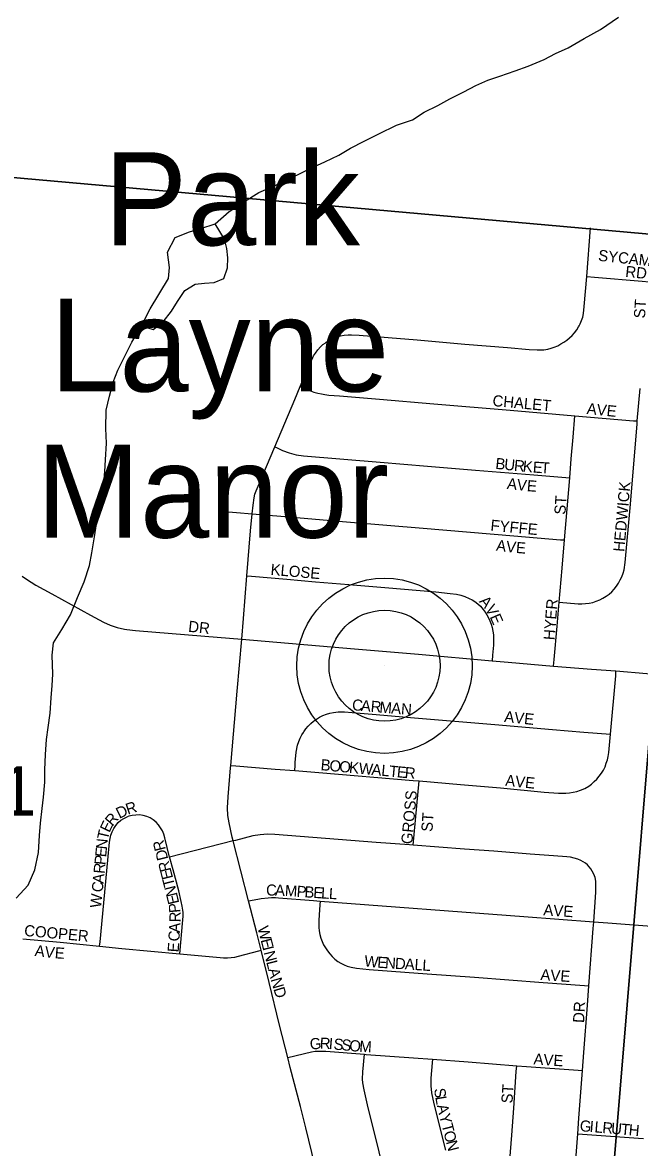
# Model space of a CAD drawing. Extents: x 0 to 680, y 0 to 440.
# Drawn here: x 150.24 to 158.43, y 273.01 to 287.97 of the extents above; entities that cross this region are included whole.
import ezdxf

# ---------------------------------------------------------------- set-up
doc = ezdxf.new("R2010")
doc.units = 0
for name, color, linetype in [('GM_X_Minor_Lake', 7, 'Continuous'), ('GM_X_Minor_River', 7, 'Continuous'), ('GM_X_Section', 7, 'Continuous'), ('GM_X_Section_Text', 7, 'Continuous'), ('GM_X_Township_Subdivision', 7, 'Continuous'), ('GM_X_Township_Subdivision_Text', 7, 'Continuous'), ('GM_X_Unincorporated', 7, 'Continuous'), ('GM_X_Unincorporated_Location', 7, 'Continuous'), ('GM_X_Unincorporated_Text', 7, 'Continuous')]:
    doc.layers.add(name, color=color, linetype=linetype)

msp = doc.modelspace()

# ---------------------------------------------------------------- linework, layer by layer
at = {"layer": 'GM_X_Minor_Lake'}
for points in [[(151.818, 283.935), (151.972, 283.886), (152.104, 283.985), (152.218, 284.126), (152.297, 284.256), (152.394, 284.403), (152.531, 284.485), (152.656, 284.501), (152.781, 284.511), (152.912, 284.563), (152.962, 284.705), (152.963, 284.836), (152.953, 284.96), (152.919, 285.086), (152.797, 285.289)], [(151.818, 283.935), (151.934, 284.159), (152.176, 284.56), (152.19, 284.709), (152.163, 284.911), (152.266, 285.106), (152.457, 285.181), (152.606, 285.226), (152.797, 285.289)]]:
    msp.add_lwpolyline(points, dxfattribs=at)
at = {"layer": 'GM_X_Minor_River'}
for points in [[(152.176, 284.56), (152.19, 284.709), (152.163, 284.911), (152.266, 285.106), (152.457, 285.181), (152.606, 285.226), (152.797, 285.289), (152.983, 285.453), (153.186, 285.587), (153.378, 285.704), (153.586, 285.796), (153.933, 285.964), (154.106, 286.045), (154.255, 286.114), (154.44, 286.201), (154.596, 286.294), (154.775, 286.387), (154.972, 286.486), (155.205, 286.602), (155.42, 286.67), (155.575, 286.775), (155.754, 286.862), (155.916, 286.949), (156.101, 287.042), (156.262, 287.129), (156.418, 287.198), (156.578, 287.25), (156.781, 287.324), (156.954, 287.387), (157.169, 287.474), (157.318, 287.555), (157.485, 287.63), (157.701, 287.752), (157.916, 287.874), (158.155, 288.038)], [(150.15, 276.322), (150.313, 276.498), (150.398, 276.699), (150.449, 276.93), (150.463, 277.155), (150.477, 277.322), (150.497, 277.517), (150.517, 277.666), (150.532, 277.867), (150.534, 278.028), (150.542, 278.236), (150.556, 278.432), (150.576, 278.592), (150.602, 278.782), (150.617, 278.989), (150.631, 279.15), (150.638, 279.304), (150.63, 279.554), (150.65, 279.72), (150.759, 279.896), (150.874, 280.091), (150.966, 280.322), (151.057, 280.528), (151.125, 280.747), (151.157, 280.913), (151.195, 281.127), (151.221, 281.299), (151.259, 281.494), (151.285, 281.643), (151.317, 281.844), (151.331, 281.998), (151.339, 282.153), (151.353, 282.372), (151.344, 282.569), (151.347, 282.812), (151.391, 282.996), (151.441, 283.185), (151.502, 283.345), (151.606, 283.546), (151.691, 283.717), (151.818, 283.935), (151.934, 284.159), (152.176, 284.56)]]:
    msp.add_lwpolyline(points, dxfattribs=at)
at = {"layer": 'GM_X_Section'}
for points in [[(144.694, 302.485), (160.808, 300.853), (159.118, 285.103), (143.238, 286.516), (144.684, 302.372)], [(143.224, 286.379), (143.238, 286.516), (159.118, 285.103), (157.8, 269.245), (141.851, 270.701)], [(159.118, 285.103), (174.94, 283.442), (173.525, 267.764), (158.298, 269.195), (157.8, 269.245)]]:
    msp.add_lwpolyline(points, close=True, dxfattribs=at)
at = {"layer": 'GM_X_Township_Subdivision'}
for points in [[(157.733, 284.59), (157.785, 285.235)], [(153.927, 283.126), (154.043, 283.399), (154.084, 283.491), (154.105, 283.532), (154.128, 283.571), (154.159, 283.614), (154.195, 283.654), (154.229, 283.684), (154.258, 283.703), (154.273, 283.714), (154.32, 283.742), (154.363, 283.764), (154.411, 283.784), (154.462, 283.801), (154.51, 283.809), (154.562, 283.815), (154.61, 283.815), (154.71, 283.81), (155.481, 283.747), (156.114, 283.691), (156.68, 283.644), (156.971, 283.62), (157.073, 283.614), (157.164, 283.616), (157.215, 283.623), (157.263, 283.636), (157.303, 283.65), (157.348, 283.668), (157.389, 283.692), (157.43, 283.716), (157.469, 283.744), (157.506, 283.774), (157.54, 283.806), (157.572, 283.842), (157.601, 283.879), (157.626, 283.919), (157.635, 283.935), (157.648, 283.961), (157.666, 284.005), (157.68, 284.05), (157.689, 284.097), (157.701, 284.19), (157.733, 284.59)], [(157.733, 284.59), (157.839, 284.581), (158.471, 284.526), (158.564, 284.518)], [(153.59, 282.326), (153.855, 282.952), (153.927, 283.126)], [(153.927, 283.126), (154.062, 283.069), (154.109, 283.051), (154.159, 283.036), (154.208, 283.027), (154.253, 283.019), (154.306, 283.012), (154.448, 283.001), (154.979, 282.956), (155.703, 282.895), (156.717, 282.81), (157.577, 282.738)], [(158.405, 282.668), (158.443, 283.098)], [(157.508, 281.912), (157.528, 282.164), (157.553, 282.454), (157.577, 282.738)], [(157.577, 282.738), (158.357, 282.672), (158.405, 282.668)], [(157.369, 280.259), (157.622, 280.237), (157.669, 280.237), (157.719, 280.24), (157.767, 280.246), (157.815, 280.256), (157.861, 280.271), (157.906, 280.289), (157.949, 280.311), (157.991, 280.337), (158.03, 280.366), (158.066, 280.398), (158.1, 280.433), (158.131, 280.471), (158.158, 280.511), (158.18, 280.554), (158.2, 280.598), (158.216, 280.644), (158.229, 280.691), (158.245, 280.787), (158.311, 281.513), (158.402, 282.627), (158.405, 282.668)], [(153.288, 281.435), (153.301, 281.548), (153.313, 281.645), (153.325, 281.695), (153.341, 281.738), (153.379, 281.831), (153.59, 282.326)], [(153.59, 282.326), (153.621, 282.311), (153.692, 282.277), (153.778, 282.245), (153.873, 282.22), (153.969, 282.205), (154.989, 282.121), (155.619, 282.068), (156.255, 282.015), (157.033, 281.95), (157.508, 281.912)], [(157.438, 281.086), (157.508, 281.912)], [(152.87, 281.469), (153.288, 281.435)], [(153.219, 280.61), (153.267, 281.207), (153.288, 281.435)], [(153.288, 281.435), (153.668, 281.402), (154.541, 281.325), (155.561, 281.241), (156.766, 281.139), (157.385, 281.09), (157.438, 281.086)], [(157.369, 280.259), (157.408, 280.71), (157.438, 281.086)], [(150.233, 280.603), (150.288, 280.563), (150.413, 280.486), (150.627, 280.369), (151.139, 280.087), (151.311, 279.994), (151.401, 279.954), (151.495, 279.923), (151.592, 279.901), (151.622, 279.897)], [(153.15, 279.766), (153.172, 280.044), (153.219, 280.61)], [(153.219, 280.61), (153.28, 280.605), (153.748, 280.566), (154.129, 280.531), (154.571, 280.493), (155.051, 280.452), (155.727, 280.395), (155.919, 280.376), (156.004, 280.365), (156.059, 280.354), (156.115, 280.336), (156.173, 280.31), (156.21, 280.29), (156.246, 280.266), (156.286, 280.239), (156.32, 280.205), (156.357, 280.163), (156.383, 280.127), (156.407, 280.089), (156.427, 280.052), (156.447, 280.01), (156.464, 279.966), (156.476, 279.921), (156.486, 279.875), (156.493, 279.826), (156.495, 279.781), (156.493, 279.688), (156.482, 279.554), (156.476, 279.478)], [(157.294, 279.41), (157.302, 279.497), (157.341, 279.938), (157.369, 280.259)], [(151.622, 279.897), (151.737, 279.882), (152.659, 279.808), (153.15, 279.766)], [(153.004, 278.089), (153.088, 279.075), (153.15, 279.766)], [(153.15, 279.766), (154.65, 279.638), (155.499, 279.566), (156.476, 279.478)], [(156.476, 279.478), (156.689, 279.46), (157.294, 279.41)], [(157.294, 279.41), (157.799, 279.37), (158.122, 279.345)], [(158.049, 278.504), (158.12, 279.281), (158.122, 279.345)], [(158.122, 279.345), (158.531, 279.309), (158.97, 279.272)], [(153.854, 278.02), (153.858, 278.088), (153.861, 278.128), (153.874, 278.264), (153.892, 278.359), (153.907, 278.406), (153.926, 278.451), (153.949, 278.495), (153.968, 278.527), (153.973, 278.535), (154, 278.575), (154.033, 278.611), (154.068, 278.645), (154.105, 278.677), (154.143, 278.705), (154.183, 278.732), (154.227, 278.754), (154.274, 278.771), (154.322, 278.785), (154.37, 278.794), (154.429, 278.801), (154.513, 278.801), (154.618, 278.793), (154.935, 278.766), (155.393, 278.724), (156.512, 278.632), (157.28, 278.568), (157.694, 278.532), (158.049, 278.504)], [(155.505, 277.882), (156.055, 277.833), (156.587, 277.791), (157.167, 277.733), (157.36, 277.721), (157.457, 277.72), (157.505, 277.725), (157.554, 277.732), (157.604, 277.743), (157.649, 277.759), (157.709, 277.783), (157.76, 277.813), (157.797, 277.84), (157.834, 277.873), (157.869, 277.907), (157.901, 277.944), (157.93, 277.984), (157.955, 278.027), (157.977, 278.071), (157.994, 278.117), (158.01, 278.163), (158.019, 278.209), (158.027, 278.262), (158.049, 278.504)], [(153.037, 277.085), (153.024, 277.136), (152.981, 277.327), (152.966, 277.424), (152.961, 277.523), (152.967, 277.67), (153.001, 278.057), (153.004, 278.089)], [(153.004, 278.089), (153.07, 278.084), (153.594, 278.041), (153.854, 278.02)], [(153.854, 278.02), (154.173, 277.995), (155.428, 277.888), (155.505, 277.882)], [(155.428, 277.027), (155.505, 277.882)], [(151.261, 275.685), (151.266, 275.742), (151.368, 276.83), (151.393, 277.069), (151.4, 277.116), (151.411, 277.163), (151.428, 277.208), (151.449, 277.251), (151.475, 277.291), (151.507, 277.328), (151.543, 277.359), (151.583, 277.385), (151.627, 277.406)], [(152.191, 276.871), (152.129, 277.126), (152.114, 277.173), (152.095, 277.217), (152.072, 277.26), (152.044, 277.3), (152.011, 277.336), (151.973, 277.367), (151.932, 277.392), (151.887, 277.411), (151.84, 277.423), (151.791, 277.43), (151.743, 277.429), (151.694, 277.424), (151.65, 277.414), (151.627, 277.406)], [(155.428, 277.027), (155.379, 277.031), (154.934, 277.065), (153.587, 277.17), (153.49, 277.173), (153.394, 277.167), (153.299, 277.151), (153.065, 277.092), (153.037, 277.085)], [(153.037, 277.085), (152.191, 276.871)], [(153.241, 276.287), (153.037, 277.085)], [(157.826, 276.011), (157.853, 276.404), (157.856, 276.498), (157.854, 276.549), (157.845, 276.597), (157.829, 276.643), (157.808, 276.685), (157.789, 276.716), (157.767, 276.742), (157.743, 276.767), (157.716, 276.788), (157.686, 276.809), (157.657, 276.825), (157.614, 276.844), (157.568, 276.858), (157.519, 276.868), (157.471, 276.872), (157.292, 276.886), (156.984, 276.909), (156.498, 276.947), (156.109, 276.975), (155.428, 277.027)], [(152.326, 275.584), (152.33, 275.632), (152.362, 275.989), (152.371, 276.085), (152.371, 276.132), (152.367, 276.165), (152.358, 276.216), (152.344, 276.279), (152.313, 276.421), (152.236, 276.702), (152.197, 276.843), (152.191, 276.871)], [(153.241, 276.287), (153.363, 276.311), (153.408, 276.321), (153.5, 276.33), (153.547, 276.334), (153.598, 276.332), (153.64, 276.33), (154.105, 276.293), (154.19, 276.286)], [(153.406, 275.633), (153.349, 275.864), (153.241, 276.287)], [(154.19, 276.286), (154.186, 276.235), (154.181, 276.168), (154.173, 276.033), (154.174, 275.936), (154.18, 275.888), (154.189, 275.841), (154.202, 275.794), (154.218, 275.749), (154.238, 275.705), (154.263, 275.663), (154.291, 275.623), (154.32, 275.585), (154.351, 275.55), (154.387, 275.514), (154.425, 275.483), (154.466, 275.458), (154.51, 275.438), (154.551, 275.421), (154.603, 275.407), (154.673, 275.392), (154.842, 275.376), (155.613, 275.317), (156.241, 275.274), (157.157, 275.204), (157.703, 275.161), (157.762, 275.157)], [(154.19, 276.286), (156.898, 276.081), (157.826, 276.011)], [(157.762, 275.157), (157.82, 275.919), (157.826, 276.011)], [(157.826, 276.011), (158.015, 275.998), (158.708, 275.945)], [(150.24, 275.784), (150.735, 275.738), (151.261, 275.685)], [(151.261, 275.685), (151.556, 275.656), (152.326, 275.584)], [(152.326, 275.584), (152.571, 275.561), (152.862, 275.533), (152.907, 275.531), (152.959, 275.531), (153.057, 275.541), (153.107, 275.551), (153.375, 275.624), (153.406, 275.633)], [(153.761, 274.207), (153.653, 274.637), (153.512, 275.204), (153.406, 275.633)], [(157.679, 274.033), (157.697, 274.271), (157.743, 274.901), (157.762, 275.157)], [(153.761, 274.207), (154.075, 274.281), (154.123, 274.289), (154.171, 274.292), (154.268, 274.289), (154.781, 274.248)], [(154.221, 272.373), (154.198, 272.468), (153.999, 273.271), (153.93, 273.554), (153.795, 274.071), (153.761, 274.207)], [(155.052, 272.634), (154.958, 273.025), (154.828, 273.536), (154.775, 273.774), (154.759, 273.87), (154.756, 273.918), (154.759, 274.016), (154.781, 274.248)], [(154.781, 274.248), (154.801, 274.246), (155.431, 274.201), (155.685, 274.182)], [(155.685, 274.182), (155.681, 274.133), (155.662, 273.929), (155.662, 273.831), (155.672, 273.734), (155.701, 273.591), (155.857, 272.975)], [(155.685, 274.182), (156.158, 274.147), (156.804, 274.097)], [(156.65, 272.046), (156.68, 272.45), (156.737, 273.174), (156.763, 273.534), (156.798, 274.019), (156.804, 274.097)], [(156.804, 274.097), (156.932, 274.087), (157.62, 274.037), (157.679, 274.033)], [(157.616, 273.191), (157.631, 273.398), (157.679, 274.033)], [(157.391, 270.25), (157.43, 270.796), (157.485, 271.506), (157.517, 271.895), (157.576, 272.671), (157.616, 273.191)], [(157.616, 273.191), (158.422, 273.132), (158.486, 273.127)]]:
    msp.add_lwpolyline(points, dxfattribs=at)
at = {"layer": 'GM_X_Unincorporated'}
for radius in [1.165, 0.738]:
    msp.add_circle((155.047, 279.414), radius, dxfattribs=at)
at = {"layer": 'GM_X_Unincorporated_Location'}
msp.add_line((155.047, 279.414), (155.047, 279.414), dxfattribs=at)

# ---------------------------------------------------------------- texts
at = {"layer": 'GM_X_Section_Text'}
msp.add_text('31', height=0.6552, rotation=0, dxfattribs=at).set_placement((149.443, 277.42))
at = {"layer": 'GM_X_Township_Subdivision_Text'}
for s, height, rotation, p in [('SYCAMORE', 0.1482, 354.0691, (157.881, 284.798)), ('RD', 0.1482, 353.994, (158.241, 284.585)), ('ST', 0.1482, 86.4258, (158.507, 284.028)), ('CHALET', 0.1482, 354.8059, (156.477, 282.867)), ('AVE', 0.1482, 354.0969, (157.729, 282.762)), ('B', 0.148, 354.3075, (156.515, 282.032)), ('U', 0.148, 354.3008, (156.632, 282.02)), ('R', 0.148, 354.2954, (156.762, 282.007)), ('K', 0.148, 354.4604, (156.879, 281.996)), ('E', 0.148, 355.7087, (157.013, 281.983)), ('T', 0.148, 356.3866, (157.118, 281.975)), ('A', 0.148, 353.4281, (156.669, 281.766)), ('V', 0.148, 353.6779, (156.799, 281.751)), ('E', 0.148, 355.3295, (156.934, 281.736)), ('HEDWICK', 0.1482, 84.8814, (158.233, 280.924)), ('ST', 0.1482, 86.4258, (157.45, 281.419)), ('FYFFE', 0.1482, 354.56, (156.45, 281.21)), ('A', 0.148, 352.9888, (156.524, 280.944)), ('V', 0.148, 354.0449, (156.656, 280.928)), ('E', 0.148, 355.2976, (156.789, 280.914)), ('KLOSE', 0.1482, 354.9208, (153.528, 280.623)), ('A', 0.148, 311.3658, (156.296, 280.265)), ('HYER', 0.1482, 85.4856, (157.307, 279.75)), ('V', 0.148, 300.4633, (156.378, 280.173)), ('DR', 0.1482, 353.6631, (152.433, 279.867)), ('E', 0.148, 293.595, (156.442, 280.065)), ('C', 0.148, 355.2716, (154.611, 278.823)), ('A', 0.148, 355.2745, (154.728, 278.813)), ('R', 0.148, 355.2716, (154.858, 278.803)), ('M', 0.148, 355.2762, (154.975, 278.793)), ('A', 0.148, 355.2736, (155.131, 278.78)), ('N', 0.148, 355.6236, (155.262, 278.769)), ('AVE', 0.1482, 354.0932, (156.633, 278.667)), ('B', 0.148, 354.6132, (154.193, 278.027)), ('O', 0.148, 354.6156, (154.31, 278.016)), ('O', 0.148, 354.6156, (154.44, 278.004)), ('K', 0.148, 354.6156, (154.57, 277.992)), ('W', 0.148, 354.6123, (154.7, 277.98)), ('A', 0.148, 354.6147, (154.869, 277.964)), ('L', 0.148, 354.6102, (154.999, 277.952)), ('T', 0.148, 354.6124, (155.103, 277.942)), ('E', 0.148, 354.6175, (155.206, 277.932)), ('R', 0.148, 355.0016, (155.311, 277.922)), ('AVE', 0.1482, 354.0936, (156.646, 277.819)), ('GROSS', 0.1482, 84.9208, (155.415, 277.037)), ('R', 0.148, 18.1124, (151.635, 277.432)), ('R', 0.148, 49.5383, (151.43, 277.272)), ('D', 0.148, 25.9003, (151.523, 277.377)), ('ST', 0.1482, 86.4254, (155.683, 277.203)), ('E', 0.148, 64.2659, (151.39, 277.187)), ('T', 0.148, 77.1897, (151.37, 277.093)), ('E', 0.148, 84.322, (151.347, 276.864)), ('N', 0.148, 84.3188, (151.358, 276.968)), ('R', 0.148, 104.3231, (152.142, 276.972)), ('P', 0.148, 84.322, (151.337, 276.76)), ('D', 0.148, 104.3144, (152.174, 276.846)), ('R', 0.148, 84.3382, (151.325, 276.644)), ('R', 0.148, 104.319, (152.213, 276.694)), ('E', 0.148, 104.3282, (152.239, 276.593)), ('A', 0.148, 84.3272, (151.312, 276.514)), ('T', 0.148, 104.3146, (152.264, 276.492)), ('C', 0.148, 84.3264, (151.301, 276.397)), ('N', 0.148, 104.3252, (152.297, 276.365)), ('C', 0.148, 359.8786, (153.473, 276.358)), ('A', 0.148, 357.8465, (153.589, 276.358)), ('M', 0.148, 356.3089, (153.719, 276.353)), ('P', 0.148, 356.2541, (153.875, 276.343)), ('B', 0.148, 356.2449, (153.979, 276.336)), ('E', 0.148, 356.2404, (154.096, 276.328)), ('L', 0.148, 356.2534, (154.2, 276.321)), ('L', 0.148, 356.2404, (154.304, 276.315)), ('W', 0.148, 84.3245, (151.28, 276.189)), ('E', 0.148, 103.319, (152.321, 276.261)), ('P', 0.148, 95.4451, (152.335, 276.135)), ('R', 0.148, 89.9584, (152.336, 276.002)), ('AVE', 0.1482, 356.0571, (157.154, 276.097)), ('COOPER', 0.1482, 354.8065, (150.254, 275.823)), ('A', 0.148, 86.4969, (152.327, 275.862)), ('W', 0.148, 284.2952, (153.357, 275.932)), ('C', 0.148, 86.3547, (152.32, 275.745)), ('A', 0.148, 352.8899, (150.393, 275.557)), ('V', 0.148, 353.4068, (150.524, 275.54)), ('E', 0.148, 356.1525, (150.661, 275.525)), ('E', 0.148, 86.364, (152.311, 275.601)), ('E', 0.148, 284.2891, (153.399, 275.768)), ('I', 0.148, 284.3073, (153.425, 275.667)), ('N', 0.148, 284.3013, (153.441, 275.604)), ('L', 0.148, 284.2847, (153.473, 275.477)), ('W', 0.148, 353.9782, (154.772, 275.418)), ('E', 0.148, 356.3172, (154.947, 275.4)), ('N', 0.148, 356.4798, (155.051, 275.393)), ('D', 0.148, 356.4789, (155.182, 275.385)), ('A', 0.148, 356.4789, (155.312, 275.377)), ('L', 0.148, 356.4731, (155.442, 275.369)), ('L', 0.148, 356.4818, (155.546, 275.362)), ('A', 0.148, 284.418, (153.499, 275.376)), ('AVE', 0.1482, 356.0569, (157.115, 275.236)), ('N', 0.148, 285.9314, (153.532, 275.245)), ('D', 0.148, 286.6826, (153.569, 275.118)), ('DR', 0.1482, 86.8218, (157.698, 274.662)), ('G', 0.148, 6.4947, (154.062, 274.308)), ('R', 0.148, 358.1175, (154.185, 274.323)), ('I', 0.148, 355.0113, (154.301, 274.319)), ('S', 0.148, 354.7883, (154.365, 274.313)), ('S', 0.148, 354.651, (154.469, 274.304)), ('O', 0.148, 354.6656, (154.573, 274.294)), ('M', 0.148, 356.3774, (154.708, 274.282)), ('AVE', 0.1482, 356.0569, (157.023, 274.114)), ('S', 0.148, 277.7689, (155.705, 273.79)), ('ST', 0.1482, 86.4254, (156.746, 273.592)), ('L', 0.148, 279.6128, (155.72, 273.681)), ('A', 0.148, 283.6982, (155.74, 273.567)), ('Y', 0.148, 284.3074, (155.771, 273.439)), ('T', 0.148, 284.3013, (155.804, 273.312)), ('G', 0.148, 355.2082, (157.637, 273.227)), ('I', 0.148, 355.2073, (157.767, 273.216)), ('L', 0.148, 355.2001, (157.832, 273.211)), ('R', 0.148, 355.2101, (157.936, 273.202)), ('U', 0.148, 355.2082, (158.053, 273.192)), ('T', 0.148, 355.2001, (158.183, 273.181)), ('H', 0.148, 354.4732, (158.286, 273.173)), ('O', 0.148, 284.3013, (155.829, 273.211)), ('N', 0.148, 284.3013, (155.862, 273.085))]:
    msp.add_text(s, height=height, rotation=rotation, dxfattribs=at).set_placement(p)
at = {"layer": 'GM_X_Unincorporated_Text'}
for s, p in [('Park', (151.321, 285.004)), ('Layne', (150.604, 283.06)), ('Manor', (150.421, 281.117))]:
    msp.add_text(s, height=1.2362, rotation=0, dxfattribs=at).set_placement(p)

doc.saveas('drawing.dxf')
